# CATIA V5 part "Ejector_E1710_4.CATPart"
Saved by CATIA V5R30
Part number: Vyhazovac_2.5x160_2
Nomenclature: E1710/2.5x160
Description: MEUSBURGER
Property "Material": "1.221"
Publications: "__DrillHole", "Base"
Bounding box of the stored display mesh (mm): x -2.499 to 2.499, y -2.499 to 2.499, z 0 to 152
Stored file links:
  E:\Bakalarka\Model\Forma_v7\Ejector_E1710_4.CATPart
  E:\dev\MoldDesign\intel_a\startup\components\MoldCatalog\Ejector\Meusburger\Ejector_E1710\TableE1710.txt
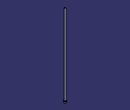
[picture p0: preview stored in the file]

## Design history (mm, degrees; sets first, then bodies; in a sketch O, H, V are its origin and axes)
Parameters
  Ref = "E1710/2.5x160" {design table}
  D1 = 2.5 mm {design table}
  D3 = 5 mm {design table}
  L = 160 mm {design table}
  L3 = 2 mm {design table}
  R = 0.3 mm {design table}
  k_d3 = 6 mm {design table}
  k_d1 = 2.7 mm {design table}
  k_F = 0.3 mm {design table}
  kl = 17 mm {design table}
  Mat = "1.221" {design table}
  HeatTreat = "ISO6751" {design table}
  Offset_Parting = 10 mm
  Anti_Rotation = "Normal"
  Anti_Rotation_D = 1.55 mm
  Anti_Rotation_D_Icut = 1.55 mm
  Add_Length_L = 0.0877 mm
  Add_Length_D3 = 0 mm
  SupplierRef = "Meusburger 2017"
  BmpRef = "F_MldEjectorD1"
  DrillHole_Length = 225 mm
  ValidationTest = false
  Anti_Rotation_D_min = 1.55 mm {= OffSet_D1 /2}
  Anti_Rotation_D_max = 2.425 mm {= D3/2-0.075mm}
  Anti_Rotation_D_ref = 1.55 mm {= Anti_Rotation_D}
  Anti_Rotation_D_Icut_ref = 1.55 mm {= Anti_Rotation_D_Icut}
  Anti_Rotation_Ref_Icut = 2.3246 mm
  Offset_L = 20 mm
  D = 2.5 mm {= D1}
  OffSet_D1 = 3.1 mm {= D1+2*R}
  OffSet_D3 = 6 mm {= D3+1mm}
  XG_Split = -30 mm
  YG_Split = 15 mm
  ZG_Split = -198 mm
  DirX_Split = 0 mm
  DirY_Split = 0 mm
  DirZ_Split = 1 mm
Set1 "BaseBody"
  Point1 "Base": (0, 0, 0)
  Plane1: type Offset, RefPlane xy-plane, Offset 225 {= DrillHole_Length}, reversed
  Sketch1 "Sketch.2" on xy-plane, origin (0, 0, 0), H (1, 0, 0), V (0, 1, 0)
    point P1 (-0.46, 1.1623)
    point P2 (0.46, 1.1623)
    construction line L1 (-0.46, 1.1623) -> (0.46, 1.1623)
    point P3 (0.46, -1.1623)
    line L2 (0.46, -1.1623) -> (0.46, 1.1623)
    point P4 (-0.46, -1.1623)
    construction line L3 (0.46, -1.1623) -> (-0.46, -1.1623)
    line L4 (-0.46, 1.1623) -> (-0.46, -1.1623)
    point P5 (-0.21, 1.1623)
    arc A1 centre (-0.21, 1.1623) radius 0.25 from (-0.21, 1.4123) to (-0.46, 1.1623) ccw
    point P7 (0.21, 1.1623)
    point P8 (0.21, 1.4123)
    arc A2 centre (0.21, 1.1623) radius 0.25 from (0.46, 1.1623) to (0.21, 1.4123) ccw
    line L5 (-0.21, 1.4123) -> (0.21, 1.4123)
    point P9 (-0.46, -1.1623)
    arc A3 centre (-0.21, -1.1623) radius 0.25 from (-0.46, -1.1623) to (-0.21, -1.4123) ccw
    point P11 (0.21, -1.4123)
    line L6 (-0.21, -1.4123) -> (0.21, -1.4123)
    point P12 (0.46, -1.1623)
    arc A4 centre (0.21, -1.1623) radius 0.25 from (0.21, -1.4123) to (0.46, -1.1623) ccw
    point P14 (-0.46, 1.1623)
    point P15 (-0.46, -1.1623)
    point P16 (0.46, 1.1623)
    point P17 (0.46, -1.1623)
    reference projected circle E1 centre (0, 0) radius 1.25 from edge [face of Shaft1 from Sketch2.L3 | face of Shaft1 from Sketch2.L4]
    reference projected circle E2 centre (0, 0) radius 1.25 from edge [face of Shaft1 from Sketch2.L3 | face of Shaft1 from Sketch2.L4]
    reference projected circle E3 centre (0, 0) radius 1.25 from edge [face of Shaft1 from Sketch2.L3 | face of Shaft1 from Sketch2.L4]
    reference projected circle E4 centre (0, 0) radius 1.25 from edge [face of Shaft1 from Sketch2.L3 | face of Shaft1 from Sketch2.L4]
    point P18 (-0.46, -1.1623)
    point P19 (-0.21, -1.4123)
    point P20 (0.21, -1.4123)
    point P21 (0.46, -1.1623)
    point P22 (-0.21, -1.4123)
    point P23 (0.21, -1.4123)
    distance P14 P15 = 2.3246 (reference)
    distance P16 P17 = 2.3246 (reference)
    distance L1 P14 = 0 (reference)
    radius A1 = 1.25
    distance L4 V = 1.56
    distance L2 V = 2.435
    distance L5 L6 = 5
    horizontal: L1 H, L3 H, L5 H
    vertical: L2 V, L4 V
    coincidence: P5 L1, P7 L1, P3 P12, P14 L4, P15 L4, P16 L2, P17 L2, P14 E1, P15 E2, P16 E3, P17 E4, P3 P21, P4 P18, P20 P23, P19 P22
    tangency: A1 L4, A2 L2, A2 L5, A1 L5
    symmetry: P1 P9 H, A1 A3 H, P8 P11 H, L5 L6 H, P2 P12 H, A2 A4 H
  DatumSurface1
Body1 "PartBody" (main body)
  Sketch2 "Sketch.1" on zx-plane, origin (0, 0, 0), H (-1, 0, 0), V (0, 0, 1)
    point P1 (0, 160)
    line L1 (1.25, 160) -> (0, 160)
    line L2 (1.25, 2) -> (1.25, 160)
    line L3 (2.5, 2) -> (1.25, 2)
    line L4 (2.5, 0) -> (2.5, 2)
    point P5 (0, 0)
    line L5 (0, 0) -> (2.5, 0)
    point P6 (0, 160)
    axis line L6 (0, 160) -> (0, 0)
    point P7 (0, 0)
    point P8 (1.25, 2)
    point P9 (1.25, 2)
    line L7 (0, 160) -> (0, 0)
    distance L5 L3 = 2 {= L3}
    distance L5 L1 = 160 {= L}
    distance L2 L6 = 1.25 {= D1 /2}
    distance L4 L6 = 2.5 {= D3 /2}
    coincidence: L6 P5, P1 L6, L5 H, L6 V, P7 O, P6 P1, P8 P9
    vertical: L2 V, L7 V
    horizontal: L1 H
  Shaft1 "Shaft.1": profile Sketch2, axis Sketch2.L6, angle 360
  Pocket1 "Pocket.1": profile Sketch1, direction (0, 0, 1), length 3, outer side, deactivated
  Pocket2 "Pocket.2": profile Sketch1, direction (0, 0, 1), length 3, outer side, deactivated
  Fillet1: radius 0.3 {= R}, on edge [face of Shaft1 from Sketch2.L2 | face of Shaft1 from Sketch2.L3]
  Pocket3: profile face of Shaft1 from Sketch2.L1, direction along face of Shaft1 from Sketch2.L1 reversed, up to face of DatumSurface1
Body2 "__DrillHole"
  Sketch3 "Sketch.3" on face of Shaft1, origin (0, 0, 0), H (1, 0, 0), V (0, -1, 0)
    point P1 (0, 0)
    reference projected point E1 (0, 0) from Point1
    coincidence: E1 P1
  Hole1 "Hole.1": placed by Sketch3, at (0, 0, 0) direction (0, 0, 1), diameter 3.1 {= OffSet_D1}, depth 140 {= L-Offset_L}
  Sketch4 "Sketch.4" on face of Shaft1, origin (0, 0, 0), H (1, 0, 0), V (0, -1, 0)
    point P1 (0, 0)
    reference projected point E1 (0, 0) from Point1
    coincidence: E1 P1
  Hole2 "Hole.2": placed by Sketch4, at (0, 0, 0) direction (0, 0, 1), diameter 2.5 {= D1}, depth 160 {= L}
  Sketch5 "Sketch.5" on face of Shaft1 from Sketch2.L3, origin (0, 0, 2), H (1, 0, 0), V (0, 1, 0)
    point P1 (0, 0)
    reference projected point E1 (0, 0) from Point1
    coincidence: E1 P1
  Hole3 "Hole.3": placed by Sketch5, at (0, 0, 2) direction (0, 0, -1), diameter 6 {= OffSet_D3}, depth 227 {= L3 +DrillHole_Length}
  Chamfer1: length 0.3 {= k_F}, angle 45, on edge [face of Hole1 | face of Hole3]
  Body3 "__Body.1"
    Pocket4 "Pocket.3": profile Sketch1, direction (0, 0, -1), length 225, opposite side length 2, deactivated
  Assemble1: tool Body3
  Chamfer2: length 0.3 {= k_F}, angle 45, on edge [start face of Pocket4 | face of Hole1], deactivated
  Body4 "__Body.2"
    Pocket5 "Pocket.4": profile Sketch1, direction (0, 0, -1), length 225, opposite side length 2, deactivated
  Assemble2: tool Body4
  Chamfer3: length 0.3 {= k_F}, angle 45, on edge [start face of Pocket5 | face of Hole1], deactivated
Relations
  design table "TableE1710", configuration 134, drives Ref, D1, D3, L, L3, R, k_d3, k_d1, k_F, kl, Mat, HeatTreat
  Offset_L = 20mm (deactivated)
  rule "Cut_Head_rule":
    let sketch_cut (length)
    let PartBody_Pocket_Sketch (Boolean)
    let I_PartBody_Pocket (Boolean)
    let D_PartBody_Pocket (Boolean)
    let N_DrillHole_Hole (Boolean)
    let N_DrillHole_Hole_Sketch (Boolean)
    let I_DrillHole_Pocket (Boolean)
    let D_DrillHole_Pocket (Boolean)
    /* --------------------------------------------------------------------------------------*/
    if Anti_Rotation =="Normal"
    {
    	sketch_cut=Anti_Rotation_D_max
    	PartBody_Pocket_Sketch = false
    	I_PartBody_Pocket = false
    	D_PartBody_Pocket = false
    	N_DrillHole_Hole = true
    	N_DrillHole_Hole_Sketch = true
    	I_DrillHole_Pocket = false
    	D_DrillHole_Pocket = false
    	Chamfer1.Activity= true
    	Chamfer2.Activity= false
    	Chamfer3.Activity= false
    }
    if Anti_Rotation == "I_Cut"
    {
    	sketch_cut=Anti_Rotation_D_Icut_ref
    	PartBody_Pocket_Sketch = true
    	I_PartBody_Pocket = true
    	D_PartBody_Pocket = false
    	N_DrillHole_Hole = false
    	N_DrillHole_Hole_Sketch = false
    	I_DrillHole_Pocket = true
    	D_DrillHole_Pocket = false
    	Chamfer1.Activity= false
    	Chamfer2.Activity= true
    	Chamfer3.Activity= false
    }
    if Anti_Rotation =="D_Cut"
    {
    	sketch_cut=Anti_Rotation_D_max
    	PartBody_Pocket_Sketch = true
    	I_PartBody_Pocket = false
    	D_PartBody_Pocket = true
    	N_DrillHole_Hole = false
    	N_DrillHole_Hole_Sketch = false
    	I_DrillHole_Pocket = false
    	D_DrillHole_Pocket = true
    	Chamfer1.Activity= false
    	Chamfer2.Activity= false
    	Chamfer3.Activity= true
    }
    /* --------------------------------------------------------------------------------------*/
    Sketch1.distance(L2 V) = sketch_cut+0.01mm
    Sketch1.distance(L4 V) =Anti_Rotation_D_ref+0.01mm
    Sketch1.radius(A1) =D/2
    Pocket4.FirstLimit.Depth = DrillHole_Length
    Pocket5.FirstLimit.Depth = DrillHole_Length
    Pocket1.FirstLimit.Depth = L3+1mm
    Pocket2.FirstLimit.Depth = L3+1mm
    Pocket4.SecondLimit.Depth = L3
    Pocket5.SecondLimit.Depth =L3
    Pocket1.Activity = I_PartBody_Pocket
    Pocket2.Activity = D_PartBody_Pocket
    Sketch1.Activity =PartBody_Pocket_Sketch
    Hole3.Activity= N_DrillHole_Hole
    Sketch5.Activity = N_DrillHole_Hole_Sketch
    Pocket4.Activity = I_DrillHole_Pocket
    Pocket5.Activity  = D_DrillHole_Pocket
  rule "Anti_Rotation_Icut_constrain":
    let Ref1(length)
    let Ref2(length)
    let Ref3(length)
    let Diam1(length)
    let Diam2(length)
    let Add_Length_Lmin (length)
    Ref1=Sketch1.distance(P14 P15)
    Ref2=Sketch1.distance(P16 P17)
    Diam1=D
    Diam2=D3
    /* --------------------------------------------------------------------*/
    if Ref1 >Ref2
    	Anti_Rotation_Ref_Icut = Ref1
    else
    	Anti_Rotation_Ref_Icut  =Ref2
    Add_Length_D3 .InferiorRange=Anti_Rotation_Ref_Icut /2+Diam1/2 -Diam2/2
    if Add_Length_D3 .InferiorRange<0mm
    	Add_Length_D3 .InferiorRange=0mm
    if ValidationTest == "true"
    	Ref3   = 2*Add_Length_L +Anti_Rotation_Ref_Icut  +2*Diam1/2
    else
    	Ref3  =Diam2+2*Add_Length_D3
    if Ref3 <Diam2
    {
    	Ref3 =Diam2
    }
    /* --------------------------------------------------------------------*/
    Sketch1.distance(L5 L6) = Ref3
    Add_Length_L .InferiorRange=Diam2/2-Anti_Rotation_Ref_Icut/2-Diam1/2
    Add_Length_Lmin=Diam2/2-Anti_Rotation_Ref_Icut/2-Diam1/2
    if Add_Length_Lmin<0mm
    	Add_Length_L .InferiorRange=0mm
    else
    	Add_Length_L .InferiorRange=Add_Length_Lmin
